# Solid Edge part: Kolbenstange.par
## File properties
Username: bmolnar
Dokumentum tartalom típus: 0
Author: bmolnar
Last saved by: bmolnar
Revision: 79
Sűrűség: 0,000 kg/m^3
Pontosság: 0,990
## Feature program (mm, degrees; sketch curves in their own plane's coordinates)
base feature "unnamed BaseFeature 1"
sketch for "unnamed Protrusion 1" plane through (54.2, 0, 0) normal (1, 0, 0) x-axis (0, 0, -1)
  circle centre (0, 0) radius 50
extrude "unnamed Protrusion 1" add finite 21.4 along +normal
sketch for "Kihúzás_2" #1 plane through (54.2, 0, 0) normal (1, 0, 0) x-axis (0, 0, -1)
  circle centre (0, 0) radius 12.5
sketch for "Kihúzás_2" #2 plane through (54.2, 0, 0) normal (1, 0, 0) x-axis (0, 0, -1)
  circle centre (0, 0) radius 50
extrude "Kihúzás_2" add finite 12.85 along -normal
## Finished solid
Body 1: solid body, 13 faces, 19 edges, 8 vertices.
  Faces by surface: plane 7, cylinder 3, cone 2, torus 1
  Edges by curve: circle 9, line 6, curve on surface 2, ellipse 2
Bounding box of the edges (mm; curved faces can reach further): 85.600 x 100.000 x 100.000, from (-10, -50, -50) to (75.6, 50, 50).
Cylindrical faces by radius (mm): R5.053 x1, R12.5 x1, R50 x1
Conical faces (half-angle, radius in mm at the cone's reference point): 45 deg R5.553 x1, 59 deg R2.5265 x1
Toroidal faces (ring radius, tube radius in mm): R10.7 r1.8 x1
Planar faces by outward normal: +x 1, +y 1, -x 2, -y 1, oblique 2
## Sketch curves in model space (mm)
circle centre (54.2, 0, 0) radius 50
circle centre (54.2, 0, 0) radius 12.5
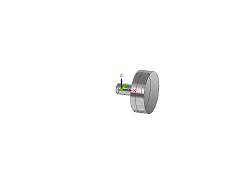
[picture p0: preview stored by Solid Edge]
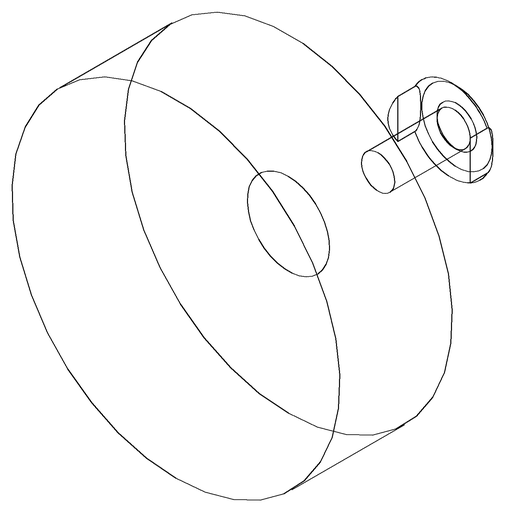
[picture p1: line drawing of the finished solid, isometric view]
